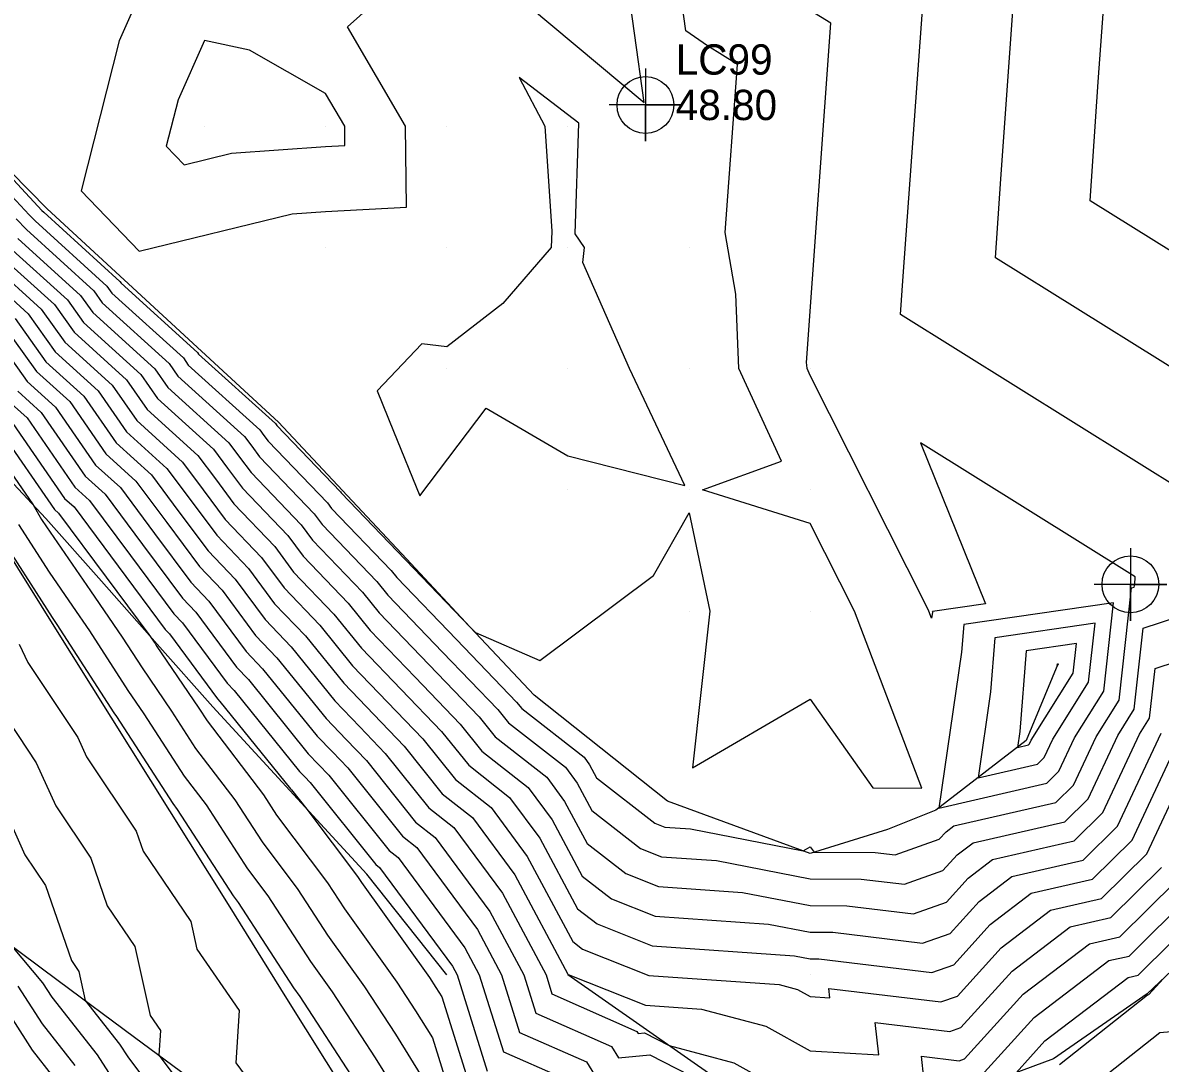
# Model space of a CAD drawing. Extents: x 2188792 to 2191981, y 386090 to 389710.
# Drawn here: x 2189865.1 to 2189959, y 387442.9 to 387528.7 of the extents above; entities that cross this region are included whole.
import ezdxf

# ---------------------------------------------------------------- set-up
doc = ezdxf.new("R2010")
doc.units = 0
for name, color, linetype in [('DTM Contours Major', 7, 'Continuous'), ('DTM Contours Minor', 7, 'Continuous'), ('Exist DTM QL2 LIDAR Elevation Point', 7, 'Continuous'), ('Exist DTM Regular Point Underwater CELL', 7, 'Continuous'), ('Exist DTM Regular Point Underwater Cogo Elevation', 7, 'Continuous'), ('Exist DTM Regular Point Underwater Cogo Number', 7, 'Continuous'), ('PH Exist DTM Breakline', 7, 'Continuous')]:
    doc.layers.add(name, color=color, linetype=linetype)

msp = doc.modelspace()

# ---------------------------------------------------------------- linework, layer by layer
at = {"layer": 'DTM Contours Major'}
for points in [[(2189860.942, 387519.353), (2189866.688, 387513.2), (2189866.83, 387513.054), (2189873.118, 387507.344), (2189873.22, 387507.201), (2189879.53, 387501.481), (2189879.617, 387501.356), (2189885.951, 387495.625), (2189886.007, 387495.55), (2189886.066, 387495.47), (2189891.337, 387489.977), (2189891.379, 387489.921), (2189896.679, 387484.404), (2189896.71, 387484.365), (2189902.032, 387478.831), (2189902.474, 387478.372), (2189907.786, 387476.074), (2189917.173, 387483.078), (2189920.1, 387488.264), (2189921.804, 387480.15), (2189920.379, 387467.208), (2189930.101, 387472.889), (2189935.255, 387465.565), (2189939.314, 387465.553), (2189933.761, 387480.15), (2189930.101, 387487.381), (2189921.209, 387490.151), (2189927.725, 387492.527), (2189924.22, 387500.152), (2189923.961, 387506.292), (2189923.086, 387511.372), (2189924.085, 387525.247), (2189921.613, 387526.78), (2189919.838, 387528.02), (2189914.142, 387568.816)], [(2189882.802, 387543.423), (2189880.096, 387547.344), (2189870.436, 387549.816), (2189870.095, 387549.488), (2189867.285, 387542.966), (2189865.146, 387540.156), (2189870.095, 387534.925), (2189873.194, 387533.254), (2189874.381, 387530.155), (2189873.062, 387527.188), (2189869.925, 387514.816), (2189874.721, 387509.85), (2189887.333, 387512.918), (2189890.097, 387513.115), (2189896.771, 387513.48), (2189896.689, 387520.154), (2189891.906, 387528.347), (2189893.954, 387530.155), (2189890.097, 387531.285), (2189884.185, 387534.244), (2189885.456, 387540.156), (2189882.802, 387543.423)], [(2189910.711, 387511.278), (2189910.997, 387520.4), (2189906.081, 387524.172), (2189908.188, 387520.154), (2189908.772, 387511.481), (2189908.729, 387510.153), (2189904.737, 387505.514), (2189900.098, 387501.949), (2189898.038, 387502.213), (2189894.341, 387498.32), (2189895.691, 387495.008), (2189897.868, 387489.668), (2189903.363, 387496.887), (2189910.099, 387492.962), (2189919.737, 387490.514), (2189915.178, 387500.152), (2189911.341, 387508.911), (2189911.463, 387510.153), (2189910.711, 387511.278)], [(2189863.273, 387509.466), (2189867.71, 387505.437), (2189869.34, 387503.152), (2189873.665, 387499.231), (2189875.364, 387496.777), (2189879.56, 387492.98), (2189880.998, 387491.049), (2189882.525, 387488.997), (2189885.905, 387485.476), (2189887.455, 387483.375), (2189890.791, 387479.903), (2189893.056, 387477.1), (2189896.345, 387473.68), (2189899.667, 387470.226), (2189901.908, 387467.428), (2189905.29, 387464.786), (2189907.774, 387461.426), (2189910.891, 387455.591), (2189912.506, 387454.339), (2189917.042, 387452.531), (2189928.815, 387451.712), (2189930.101, 387451.46), (2189930.798, 387451.459), (2189940.126, 387450.333), (2189941.943, 387450.976), (2189944.94, 387454.288), (2189948.346, 387456.874), (2189953.393, 387458.029), (2189956.665, 387461.26), (2189960.354, 387469.136)], [(2189862.301, 387503.531), (2189865.46, 387499.104), (2189867.801, 387496.982), (2189871.111, 387492.198), (2189873.17, 387490.336), (2189875.989, 387486.548), (2189878.984, 387482.525), (2189880.472, 387480.975), (2189883.53, 387476.829), (2189884.902, 387475.401), (2189889.401, 387469.836), (2189890.657, 387468.53), (2189891.926, 387467.211), (2189896.436, 387461.58), (2189897.617, 387460.657), (2189902.633, 387453.872), (2189904.622, 387450.147), (2189906.114, 387445.392), (2189911.62, 387442.957), (2189912.646, 387441.307)], [(2189861.936, 387494.733), (2189865.965, 387488.911), (2189866.662, 387487.713), (2189867.06, 387487.095), (2189870.687, 387481.821), (2189873.315, 387477.999), (2189874.954, 387475.461), (2189877.373, 387471.907), (2189879.367, 387468.822), (2189882.605, 387464.578), (2189884.856, 387461.105), (2189887.8, 387457.191), (2189890.258, 387453.408), (2189893.315, 387449.148), (2189895.86, 387445.237), (2189898.133, 387441.581)], [(2189955.14, 387480.829), (2189942.765, 387479.034), (2189942.586, 387476.764), (2189940.713, 387463.907), (2189949.617, 387465.944), (2189950.625, 387466.94), (2189951.914, 387469.691), (2189954.332, 387473.544), (2189955.14, 387480.829)], [(2189862.785, 387465.551), (2189865.285, 387460.032), (2189866.981, 387457.503), (2189869.116, 387451.324), (2189869.722, 387450.429), (2189870.255, 387448.029), (2189873.095, 387444.419), (2189873.766, 387443.369), (2189877.706, 387438.14)], [(2189947.084, 387442.068), (2189949.477, 387444.712), (2189956.342, 387449.924), (2189957.168, 387450.113), (2189962.705, 387455.58)]]:
    msp.add_lwpolyline(points, dxfattribs=at)
at = {"layer": 'DTM Contours Minor'}
for points in [[(2189965.773, 387496.586), (2189945.388, 387509.305), (2189945.822, 387515.801), (2189947.237, 387535.442), (2189937.221, 387541.65), (2189930.029, 387546.676), (2189926.552, 387571.576), (2189898.323, 387573.82), (2189895.789, 387576.832), (2189893.261, 387579.451), (2189888.191, 387586.849), (2189886.412, 387588.67), (2189879.31, 387595.804), (2189877.525, 387597.633), (2189875.642, 387599.562)], [(2189970.196, 387503.396), (2189953.216, 387513.992), (2189953.871, 387523.813), (2189954.954, 387538.84), (2189942.423, 387546.607), (2189933.426, 387552.894), (2189930.688, 387572.497), (2189898.665, 387575.042), (2189896.619, 387577.474), (2189894.578, 387579.588), (2189888.835, 387587.969), (2189887.658, 387589.174), (2189879.578, 387597.29), (2189878.402, 387598.495)], [(2189961.349, 387489.775), (2189937.561, 387504.619), (2189937.772, 387507.788), (2189939.519, 387532.044), (2189932.018, 387536.694), (2189926.632, 387540.457), (2189922.415, 387570.656), (2189897.98, 387572.598), (2189894.958, 387576.191)], [(2189862.966, 387557.286), (2189865.806, 387560.158), (2189861.394, 387568.86), (2189870.095, 387562.611), (2189874.856, 387560.158), (2189880.096, 387556.119), (2189881.9, 387550.018), (2189884.793, 387545.827), (2189889.399, 387540.156), (2189889.208, 387539.267), (2189890.097, 387538.822), (2189891.984, 387538.269), (2189899.315, 387536.419), (2189916.397, 387522.118), (2189910.005, 387567.895), (2189896.954, 387568.933), (2189892.466, 387574.267)], [(2189860.234, 387518.618), (2189865.622, 387512.849), (2189866.119, 387512.336), (2189872.037, 387506.963), (2189872.444, 387506.391), (2189878.357, 387501.031), (2189878.766, 387500.44), (2189884.673, 387495.096), (2189885.005, 387494.649), (2189885.358, 387494.175), (2189890.251, 387489.077), (2189890.594, 387488.612), (2189895.501, 387483.504), (2189895.979, 387482.912), (2189900.895, 387477.801), (2189905.86, 387472.638), (2189906.286, 387472.106), (2189911.428, 387468.09), (2189911.887, 387467.469), (2189912.463, 387466.391), (2189917.281, 387462.656), (2189918.094, 387462.332), (2189920.205, 387462.185), (2189929.506, 387460.367), (2189930.101, 387460.714), (2189930.428, 387460.25), (2189935.467, 387460.24), (2189937.117, 387460.041), (2189940.747, 387461.326), (2189941.31, 387461.948), (2189941.95, 387462.434), (2189950.372, 387464.361), (2189951.833, 387465.804), (2189953.701, 387469.791), (2189955.591, 387472.803), (2189956.617, 387482.058), (2189956.85, 387482.135), (2189956.905, 387482.349), (2189956.926, 387482.965), (2189939.201, 387494.024), (2189944.576, 387480.751), (2189940.188, 387480.114), (2189940.182, 387480.041), (2189940.115, 387479.576), (2189939.896, 387480.15), (2189939.686, 387480.566), (2189930.101, 387499.578), (2189929.837, 387500.152), (2189929.825, 387500.428), (2189929.786, 387500.656), (2189931.802, 387528.645), (2189926.816, 387531.737)], [(2189891.672, 387520.154), (2189890.097, 387522.852), (2189883.817, 387526.435), (2189880.096, 387527.219), (2189877.922, 387522.329), (2189876.952, 387518.504), (2189878.434, 387516.969), (2189882.333, 387517.917), (2189890.097, 387518.472), (2189891.692, 387518.559), (2189891.672, 387520.154)], [(2189864.556, 387512.498), (2189865.408, 387511.619), (2189870.955, 387506.581), (2189871.668, 387505.581), (2189877.184, 387500.581), (2189877.915, 387499.524), (2189883.395, 387494.567), (2189884.003, 387493.749), (2189884.65, 387492.881), (2189889.164, 387488.176), (2189889.809, 387487.303), (2189894.323, 387482.604), (2189895.248, 387481.459), (2189899.757, 387476.771), (2189904.312, 387472.035), (2189905.192, 387470.936), (2189909.893, 387467.264), (2189910.859, 387465.958), (2189912.07, 387463.691), (2189916.087, 387460.577), (2189917.831, 387459.882), (2189922.357, 387459.567), (2189930.101, 387458.053), (2189934.3, 387458.045), (2189937.869, 387457.614), (2189941.046, 387458.739), (2189942.217, 387460.033), (2189943.549, 387461.044), (2189951.127, 387462.778), (2189953.041, 387464.668), (2189955.487, 387469.891), (2189956.85, 387472.063), (2189957.59, 387478.735), (2189960.431, 387479.674)], [(2189864.696, 387510.901), (2189869.873, 387506.2), (2189870.892, 387504.772), (2189876.011, 387500.131), (2189877.065, 387498.608), (2189882.117, 387494.038), (2189883.002, 387492.849), (2189883.942, 387491.586), (2189888.078, 387487.276), (2189889.024, 387485.993), (2189893.146, 387481.703), (2189894.518, 387480.006), (2189898.62, 387475.741), (2189902.763, 387471.432), (2189904.097, 387469.767), (2189908.359, 387466.438), (2189909.83, 387464.447), (2189911.677, 387460.991), (2189914.893, 387458.497), (2189917.568, 387457.431), (2189924.51, 387456.948), (2189930.101, 387455.856), (2189933.133, 387455.85), (2189938.621, 387455.187), (2189941.345, 387456.151), (2189943.125, 387458.118), (2189945.148, 387459.654), (2189951.882, 387461.195), (2189954.249, 387463.532), (2189957.274, 387469.991), (2189958.11, 387471.322), (2189958.563, 387475.411), (2189964.012, 387477.213)], [(2189863.985, 387510.184), (2189868.792, 387505.819), (2189870.116, 387503.962), (2189874.838, 387499.681), (2189876.214, 387497.693), (2189880.838, 387493.509), (2189882, 387491.949), (2189883.233, 387490.292), (2189886.991, 387486.376), (2189888.239, 387484.684), (2189891.968, 387480.803), (2189893.787, 387478.553), (2189897.482, 387474.711), (2189901.215, 387470.829), (2189903.003, 387468.597), (2189906.824, 387465.612), (2189908.802, 387462.936), (2189911.284, 387458.291), (2189913.699, 387456.418), (2189917.305, 387454.981), (2189926.662, 387454.33), (2189930.101, 387453.658), (2189931.965, 387453.654), (2189939.374, 387452.76), (2189941.644, 387453.564), (2189944.032, 387456.203), (2189946.747, 387458.264), (2189952.637, 387459.612), (2189955.457, 387462.396), (2189959.061, 387470.091)], [(2189862.562, 387508.748), (2189866.628, 387505.056), (2189868.564, 387502.343), (2189872.493, 387498.782), (2189874.513, 387495.861), (2189878.282, 387492.451), (2189879.996, 387490.149), (2189881.817, 387487.703), (2189884.818, 387484.576), (2189886.67, 387482.066), (2189889.613, 387479.002), (2189892.325, 387475.647), (2189895.207, 387472.65), (2189898.119, 387469.623), (2189900.814, 387466.258), (2189903.755, 387463.961), (2189906.746, 387459.915), (2189910.498, 387452.891), (2189911.312, 387452.26), (2189916.779, 387450.081), (2189927.522, 387449.333), (2189929.045, 387448.933), (2189930.098, 387448.345), (2189931.724, 387448.249), (2189931.64, 387449.021), (2189940.878, 387447.906), (2189942.242, 387448.389), (2189945.847, 387452.373), (2189949.945, 387455.484), (2189954.148, 387456.445), (2189957.873, 387460.124), (2189960.955, 387466.704)], [(2189861.851, 387508.031), (2189865.547, 387504.675), (2189867.788, 387501.533), (2189871.32, 387498.332), (2189873.663, 387494.945), (2189877.004, 387491.922), (2189878.994, 387489.249), (2189881.109, 387486.409), (2189883.732, 387483.675), (2189885.885, 387480.757), (2189888.435, 387478.102), (2189891.594, 387474.195), (2189894.07, 387471.62), (2189896.57, 387469.02), (2189899.719, 387465.088), (2189902.221, 387463.135), (2189905.717, 387458.404), (2189910.105, 387450.191), (2189910.118, 387450.181), (2189916.516, 387447.631), (2189921.114, 387447.311), (2189926.422, 387445.915), (2189930.09, 387443.867), (2189935.756, 387443.532), (2189935.466, 387446.223), (2189941.631, 387445.479), (2189942.54, 387445.801), (2189946.755, 387450.458), (2189951.545, 387454.094), (2189954.903, 387454.862), (2189959.081, 387458.988)], [(2189863.383, 387503.912), (2189866.236, 387499.914), (2189868.974, 387497.432), (2189871.962, 387493.114), (2189874.448, 387490.865), (2189876.991, 387487.449), (2189879.692, 387483.82), (2189881.559, 387481.875), (2189884.315, 387478.138), (2189886.08, 387476.301), (2189890.132, 387471.289), (2189891.794, 387469.56), (2189893.474, 387467.814), (2189897.53, 387462.749), (2189899.152, 387461.483), (2189903.661, 387455.382), (2189906.458, 387450.147), (2189907.45, 387446.986), (2189913.707, 387444.218), (2189914.278, 387443.301), (2189916.861, 387443.554), (2189922.381, 387440.714)], [(2189864.465, 387504.293), (2189867.012, 387500.723), (2189870.147, 387497.882), (2189872.812, 387494.03), (2189875.726, 387491.393), (2189877.993, 387488.349), (2189880.401, 387485.114), (2189882.645, 387482.775), (2189885.1, 387479.447), (2189887.258, 387477.202), (2189890.863, 387472.742), (2189892.932, 387470.59), (2189895.022, 387468.417), (2189898.625, 387463.919), (2189900.686, 387462.309), (2189904.689, 387456.893), (2189908.293, 387450.147), (2189908.785, 387448.579), (2189915.794, 387445.48), (2189915.909, 387445.295), (2189916.428, 387445.346), (2189918.458, 387444.302), (2189923.8, 387442.897), (2189930.083, 387439.389)], [(2189864.684, 387498.294), (2189866.628, 387496.532), (2189870.261, 387491.282), (2189871.892, 387489.807), (2189874.987, 387485.648), (2189878.276, 387481.231), (2189879.386, 387480.074), (2189882.746, 387475.52), (2189883.725, 387474.501), (2189888.67, 387468.383), (2189889.519, 387467.5), (2189890.377, 387466.608), (2189895.341, 387460.41), (2189896.083, 387459.831), (2189901.604, 387452.361), (2189902.787, 387450.147), (2189904.779, 387443.798), (2189909.534, 387441.696)], [(2189863.908, 387497.485), (2189865.455, 387496.082), (2189869.41, 387490.366), (2189870.614, 387489.278), (2189873.986, 387484.748), (2189877.568, 387479.936), (2189878.299, 387479.174), (2189881.961, 387474.211), (2189882.547, 387473.6), (2189887.939, 387466.93), (2189888.382, 387466.47), (2189888.829, 387466.004), (2189894.247, 387459.241), (2189894.548, 387459.005), (2189900.576, 387450.85), (2189900.952, 387450.147), (2189903.443, 387442.204)], [(2189864.282, 387495.633), (2189868.56, 387489.451), (2189869.336, 387488.749), (2189872.984, 387483.848), (2189876.859, 387478.642), (2189877.212, 387478.274), (2189881.176, 387472.901), (2189881.37, 387472.7), (2189887.208, 387465.477), (2189887.244, 387465.439), (2189887.281, 387465.401), (2189888.544, 387463.824), (2189892.722, 387458.269), (2189893.056, 387457.755), (2189898.667, 387449.936), (2189899.204, 387449.111), (2189899.683, 387448.34), (2189902.108, 387440.611)], [(2189863.109, 387495.183), (2189867.709, 387488.535), (2189868.057, 387488.22), (2189871.982, 387482.948), (2189875.503, 387478.218), (2189876.018, 387477.469), (2189876.121, 387477.311), (2189879.64, 387472.139), (2189880.311, 387471.101), (2189884.98, 387464.981), (2189886.053, 387463.325), (2189890.261, 387457.73), (2189891.657, 387455.581), (2189895.991, 387449.542), (2189897.532, 387447.174), (2189898.908, 387444.96), (2189900.773, 387439.017)], [(2189864.751, 387487.3), (2189867.291, 387483.357), (2189869.216, 387480.557), (2189870.612, 387478.529), (2189873.788, 387473.611), (2189875.106, 387471.675), (2189878.423, 387466.543), (2189880.23, 387464.175), (2189883.66, 387458.885), (2189885.34, 387456.651), (2189888.86, 387451.234), (2189890.64, 387448.753), (2189894.189, 387443.3), (2189897.357, 387438.202)], [(2189862.839, 387486.887), (2189867.522, 387479.62), (2189867.746, 387479.294), (2189867.908, 387479.059), (2189872.622, 387471.762), (2189872.839, 387471.443), (2189877.479, 387464.265), (2189877.855, 387463.772), (2189882.463, 387456.664), (2189882.879, 387456.112), (2189887.461, 387449.061), (2189887.964, 387448.359), (2189892.517, 387441.363)], [(2189953.612, 387479.154), (2189945.342, 387477.954), (2189944.989, 387473.487), (2189943.957, 387466.405), (2189948.862, 387467.527), (2189949.417, 387468.076), (2189950.127, 387469.591), (2189953.073, 387474.284), (2189953.612, 387479.154)], [(2189864.797, 387477.432), (2189865.509, 387475.917), (2189869.64, 387469.722), (2189870.356, 387468.142), (2189874.471, 387462.006), (2189875.046, 387460.342), (2189878.967, 387454.551), (2189879.474, 387452.266), (2189882.973, 387447.202), (2189882.678, 387442.894), (2189884.536, 387440.384)], [(2189952.085, 387477.478), (2189947.919, 387476.873), (2189947.392, 387470.21), (2189947.202, 387468.903), (2189948.106, 387469.11), (2189948.209, 387469.212), (2189948.34, 387469.491), (2189951.813, 387475.025), (2189952.085, 387477.478)], [(2189950.485, 387475.656), (2189950.496, 387475.793), (2189950.558, 387475.802), (2189950.554, 387475.765), (2189950.485, 387475.656)], [(2189863.156, 387472.219), (2189866.212, 387467.637), (2189867.82, 387464.087), (2189870.726, 387459.755), (2189872.081, 387455.833), (2189874.344, 387452.49), (2189875.607, 387446.802), (2189876.472, 387445.55), (2189876.334, 387443.527), (2189879.423, 387439.426)], [(2189939.682, 387439.794), (2189939.291, 387443.425), (2189942.383, 387443.052), (2189942.839, 387443.214), (2189947.662, 387448.543), (2189953.144, 387452.704), (2189955.658, 387453.279), (2189960.289, 387457.852)], [(2189943.138, 387440.626), (2189948.57, 387446.628), (2189954.743, 387451.314), (2189956.413, 387451.696), (2189961.497, 387456.716)], [(2189864.176, 387452.532), (2189866.741, 387449.495), (2189867.512, 387448.292), (2189871.247, 387443.545), (2189872.917, 387440.931)], [(2189950.672, 387442.747), (2189957.929, 387448.497), (2189957.968, 387448.501), (2189958.048, 387448.514), (2189959.221, 387449.811)], [(2189862.671, 387448.927), (2189865.874, 387443.928), (2189867.551, 387441.797)], [(2189864.706, 387449.211), (2189866.693, 387446.11), (2189869.399, 387442.671)], [(2189952.895, 387440.599), (2189958.943, 387445.392), (2189960.837, 387445.543)]]:
    msp.add_lwpolyline(points, dxfattribs=at)
at = {"layer": 'Exist DTM QL2 LIDAR Elevation Point'}
for p, q in [((2189880.096, 387520.154), (2189880.096, 387520.154)), ((2189890.097, 387520.154), (2189890.097, 387520.154)), ((2189900.098, 387520.154), (2189900.098, 387520.154)), ((2189910.099, 387520.154), (2189910.099, 387520.154)), ((2189890.097, 387510.153), (2189890.097, 387510.153)), ((2189900.098, 387510.153), (2189900.098, 387510.153)), ((2189910.099, 387510.153), (2189910.099, 387510.153)), ((2189920.1, 387510.153), (2189920.1, 387510.153)), ((2189900.098, 387500.152), (2189900.098, 387500.152)), ((2189910.099, 387500.152), (2189910.099, 387500.152)), ((2189920.1, 387500.152), (2189920.1, 387500.152)), ((2189930.101, 387500.152), (2189930.101, 387500.152)), ((2189910.099, 387490.151), (2189910.099, 387490.151)), ((2189920.1, 387490.151), (2189920.1, 387490.151)), ((2189930.101, 387490.151), (2189930.101, 387490.151)), ((2189920.1, 387480.15), (2189920.1, 387480.15)), ((2189930.101, 387480.15), (2189930.101, 387480.15)), ((2189940.102, 387480.15), (2189940.102, 387480.15)), ((2189930.101, 387450.147), (2189930.101, 387450.147))]:
    msp.add_line(p, q, dxfattribs=at)
at = {"layer": 'Exist DTM Regular Point Underwater CELL'}
for points in [[(2189916.499, 387524.907), (2189916.499, 387518.907), (2189916.499, 387521.907), (2189919.499, 387521.907), (2189913.499, 387521.907)], [(2189956.53, 387485.355), (2189956.53, 387479.355), (2189956.53, 387482.355), (2189959.53, 387482.355), (2189953.53, 387482.355)]]:
    msp.add_lwpolyline(points, dxfattribs=at)
for centre in [(2189916.499, 387521.907), (2189956.53, 387482.355)]:
    msp.add_circle(centre, 2.344, dxfattribs=at)
at = {"layer": 'PH Exist DTM Breakline'}
for points in [[(2189792.228, 387553.238), (2189796.936, 387546.389), (2189801.645, 387539.539), (2189806.354, 387532.69), (2189811.063, 387525.84), (2189815.771, 387518.991), (2189820.568, 387512.164), (2189825.365, 387505.338), (2189830.162, 387498.511), (2189835.423, 387491.15), (2189840.684, 387483.789), (2189845.945, 387476.428), (2189851.206, 387469.067), (2189856.467, 387461.706), (2189861.728, 387454.345), (2189868.032, 387449.676), (2189874.336, 387445.006), (2189880.64, 387440.337), (2189886.944, 387435.668), (2189892.374, 387427.098), (2189895.61, 387418.039), (2189892.854, 387409.091), (2189890.097, 387400.143)], [(2189900.098, 387450.147), (2189893.497, 387458.439), (2189887.143, 387465.348), (2189880.789, 387472.256), (2189876.198, 387477.434), (2189871.608, 387482.612), (2189867.017, 387487.789), (2189860.884, 387494.329), (2189854.751, 387500.869), (2189849.602, 387507.572), (2189844.453, 387514.275), (2189839.303, 387520.978), (2189834.5, 387526.886), (2189829.696, 387532.793), (2189824.893, 387538.701), (2189820.089, 387544.609)], [(2189950.535, 387475.777), (2189947.936, 387469.468), (2189940.47, 387463.72), (2189936.47, 387462.127), (2189930.101, 387460.148), (2189918.324, 387464.473), (2189912.819, 387468.839), (2189907.315, 387473.205), (2189902.039, 387478.837), (2189896.762, 387484.468), (2189891.486, 387490.1), (2189886.21, 387495.732), (2189879.845, 387501.602), (2189873.48, 387507.471), (2189867.115, 387513.341), (2189861.067, 387519.482)], [(2189964.012, 387429.863), (2189955.298, 387425.32), (2189945.315, 387422.193), (2189932.376, 387419.238), (2189924.047, 387419.702), (2189917.02, 387419.983), (2189912.515, 387420.153), (2189908.556, 387421.235), (2189900.907, 387426.952), (2189896.327, 387433.712), (2189891.748, 387440.472), (2189886.909, 387448.203), (2189882.07, 387455.934), (2189877.231, 387463.666), (2189872.392, 387471.397), (2189867.553, 387479.128), (2189862.714, 387486.86), (2189857.875, 387494.591)], [(2189975.499, 387469.317), (2189970.105, 387460.148), (2189964.006, 387454.356), (2189957.907, 387448.563), (2189950.186, 387443.216), (2189943.14, 387440.61), (2189939.074, 387439.65), (2189930.083, 387439.298), (2189922.54, 387441.448), (2189916.319, 387445.798), (2189910.099, 387450.147)]]:
    msp.add_lwpolyline(points, dxfattribs=at)

# ---------------------------------------------------------------- texts
at = {"layer": 'Exist DTM Regular Point Underwater Cogo Elevation'}
msp.add_text('48.80', height=2.5, dxfattribs=at).set_placement((2189918.999, 387520.657))
at = {"layer": 'Exist DTM Regular Point Underwater Cogo Number'}
msp.add_text('LC99', height=2.5, dxfattribs=at).set_placement((2189918.999, 387524.407))

doc.saveas('drawing.dxf')
